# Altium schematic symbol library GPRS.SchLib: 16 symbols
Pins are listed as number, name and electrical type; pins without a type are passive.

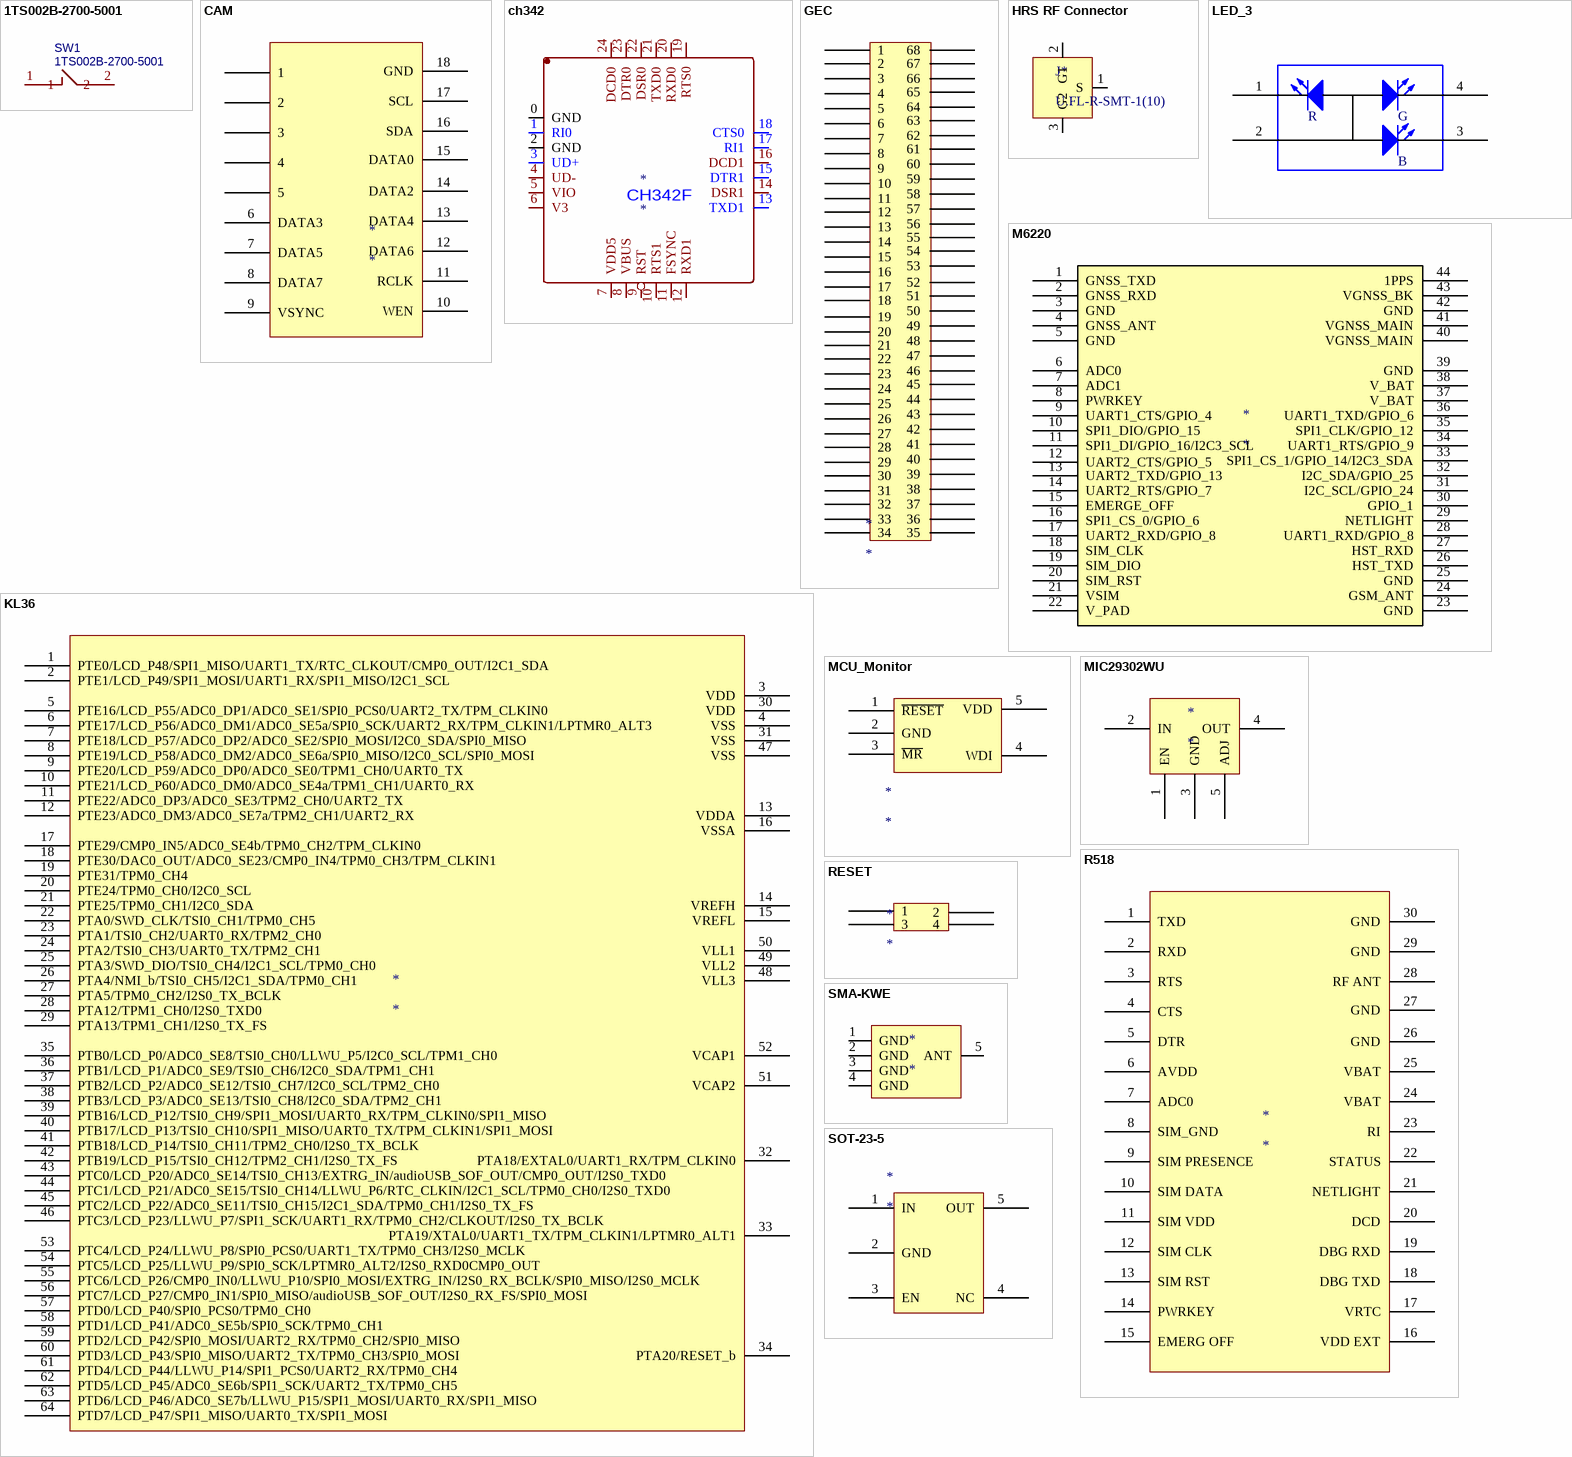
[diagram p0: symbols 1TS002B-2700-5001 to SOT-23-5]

## 1TS002B-2700-5001
designator SW1
轻触开关（贴片式，上按）; BOM_Manufacturer: HYP; Contributor: LCSC
footprint SW-SMD_L6.0-W3.5-LS8.0
pins: 1, 2

## CAM
designator *
footprint IDC2X9
pins: 4, 5, 6 DATA3, 7 DATA5, 8 DATA7, 9 VSYNC, 10 WEN, 11 RCLK, 12 DATA6, 13 DATA4, 14 DATA2, 15 DATA0, 16 SDA, 17 SCL, 18 GND, ?1 1, ?2 2, ?3 3

## ch342
designator *
footprint ch342
footprint ch342
pins: 0 GND, 1 RI0, 2 GND, 3 UD+, 4 UD-, 5 VIO, 6 V3, 7 VDD5, 8 VBUS, 9 RST, 10 RTS1, 11 FSYNC, 12 RXD1, 13 TXD1, 14 DSR1, 15 DTR1, 16 DCD1, 17 RI1, 18 CTS0, 19 RTS0, 20 RXD0, 21 TXD0, 22 DSR0, 23 DTR0, 24 DCD0

## GEC
designator *
pins: 1, 2, 3, 4, 5, 6, 7, 8, 9, 10, 11, 12, 13, 14, 15, 16, 17, 18, 19, 20, 21, 22, 23, 24, 25, 26, 27, 28, 29, 30, 31, 32, 33, 34, 35, 36, 37, 38, 39, 40, 41, 42, 43, 44, 45, 46, 47, 48, 49, 50, 51, 52, 53, 54, 55, 56, 57, 58, 59, 60, 61, 62, 63, 64, 65, 66, 67, 68

## HRS RF Connector
designator J*, comment U.FL-R-SMT-1(10)
footprint HRSRFCONNECTOR (Footprint not found)
pins: 1 S, 2 G1, 3 G2

## KL36
designator *
footprint LQFP64
pins: 1 PTE0/LCD_P48/SPI1_MISO/UART1_TX/RTC_CLKOUT/CMP0_OUT/I2C1_SDA, 2 PTE1/LCD_P49/SPI1_MOSI/UART1_RX/SPI1_MISO/I2C1_SCL, 3 VDD, 4 VSS, 5 PTE16/LCD_P55/ADC0_DP1/ADC0_SE1/SPI0_PCS0/UART2_TX/TPM_CLKIN0, 6 PTE17/LCD_P56/ADC0_DM1/ADC0_SE5a/SPI0_SCK/UART2_RX/TPM_CLKIN1/LPTMR0_ALT3, 7 PTE18/LCD_P57/ADC0_DP2/ADC0_SE2/SPI0_MOSI/I2C0_SDA/SPI0_MISO, 8 PTE19/LCD_P58/ADC0_DM2/ADC0_SE6a/SPI0_MISO/I2C0_SCL/SPI0_MOSI, 9 PTE20/LCD_P59/ADC0_DP0/ADC0_SE0/TPM1_CH0/UART0_TX, 10 PTE21/LCD_P60/ADC0_DM0/ADC0_SE4a/TPM1_CH1/UART0_RX, 11 PTE22/ADC0_DP3/ADC0_SE3/TPM2_CH0/UART2_TX, 12 PTE23/ADC0_DM3/ADC0_SE7a/TPM2_CH1/UART2_RX, 13 VDDA, 14 VREFH, 15 VREFL, 16 VSSA, 17 PTE29/CMP0_IN5/ADC0_SE4b/TPM0_CH2/TPM_CLKIN0, 18 PTE30/DAC0_OUT/ADC0_SE23/CMP0_IN4/TPM0_CH3/TPM_CLKIN1, 19 PTE31/TPM0_CH4, 20 PTE24/TPM0_CH0/I2C0_SCL, 21 PTE25/TPM0_CH1/I2C0_SDA, 22 PTA0/SWD_CLK/TSI0_CH1/TPM0_CH5, 23 PTA1/TSI0_CH2/UART0_RX/TPM2_CH0, 24 PTA2/TSI0_CH3/UART0_TX/TPM2_CH1, 25 PTA3/SWD_DIO/TSI0_CH4/I2C1_SCL/TPM0_CH0, 26 PTA4/NMI_b/TSI0_CH5/I2C1_SDA/TPM0_CH1, 27 PTA5/TPM0_CH2/I2S0_TX_BCLK, 28 PTA12/TPM1_CH0/I2S0_TXD0, 29 PTA13/TPM1_CH1/I2S0_TX_FS, 30 VDD, 31 VSS, 32 PTA18/EXTAL0/UART1_RX/TPM_CLKIN0, 33 PTA19/XTAL0/UART1_TX/TPM_CLKIN1/LPTMR0_ALT1, 34 PTA20/RESET_b, 35 PTB0/LCD_P0/ADC0_SE8/TSI0_CH0/LLWU_P5/I2C0_SCL/TPM1_CH0, 36 PTB1/LCD_P1/ADC0_SE9/TSI0_CH6/I2C0_SDA/TPM1_CH1, 37 PTB2/LCD_P2/ADC0_SE12/TSI0_CH7/I2C0_SCL/TPM2_CH0, 38 PTB3/LCD_P3/ADC0_SE13/TSI0_CH8/I2C0_SDA/TPM2_CH1, 39 PTB16/LCD_P12/TSI0_CH9/SPI1_MOSI/UART0_RX/TPM_CLKIN0/SPI1_MISO, 40 PTB17/LCD_P13/TSI0_CH10/SPI1_MISO/UART0_TX/TPM_CLKIN1/SPI1_MOSI, 41 PTB18/LCD_P14/TSI0_CH11/TPM2_CH0/I2S0_TX_BCLK, 42 PTB19/LCD_P15/TSI0_CH12/TPM2_CH1/I2S0_TX_FS, 43 PTC0/LCD_P20/ADC0_SE14/TSI0_CH13/EXTRG_IN/audioUSB_SOF_OUT/CMP0_OUT/I2S0_TXD0, 44 PTC1/LCD_P21/ADC0_SE15/TSI0_CH14/LLWU_P6/RTC_CLKIN/I2C1_SCL/TPM0_CH0/I2S0_TXD0, 45 PTC2/LCD_P22/ADC0_SE11/TSI0_CH15/I2C1_SDA/TPM0_CH1/I2S0_TX_FS, 46 PTC3/LCD_P23/LLWU_P7/SPI1_SCK/UART1_RX/TPM0_CH2/CLKOUT/I2S0_TX_BCLK, 47 VSS, 48 VLL3, 49 VLL2, 50 VLL1, 51 VCAP2, 52 VCAP1, 53 PTC4/LCD_P24/LLWU_P8/SPI0_PCS0/UART1_TX/TPM0_CH3/I2S0_MCLK, 54 PTC5/LCD_P25/LLWU_P9/SPI0_SCK/LPTMR0_ALT2/I2S0_RXD0CMP0_OUT, 55 PTC6/LCD_P26/CMP0_IN0/LLWU_P10/SPI0_MOSI/EXTRG_IN/I2S0_RX_BCLK/SPI0_MISO/I2S0_MCLK, 56 PTC7/LCD_P27/CMP0_IN1/SPI0_MISO/audioUSB_SOF_OUT/I2S0_RX_FS/SPI0_MOSI, 57 PTD0/LCD_P40/SPI0_PCS0/TPM0_CH0, 58 PTD1/LCD_P41/ADC0_SE5b/SPI0_SCK/TPM0_CH1, 59 PTD2/LCD_P42/SPI0_MOSI/UART2_RX/TPM0_CH2/SPI0_MISO, 60 PTD3/LCD_P43/SPI0_MISO/UART2_TX/TPM0_CH3/SPI0_MOSI, 61 PTD4/LCD_P44/LLWU_P14/SPI1_PCS0/UART2_RX/TPM0_CH4, 62 PTD5/LCD_P45/ADC0_SE6b/SPI1_SCK/UART2_TX/TPM0_CH5, 63 PTD6/LCD_P46/ADC0_SE7b/LLWU_P15/SPI1_MOSI/UART0_RX/SPI1_MISO, 64 PTD7/LCD_P47/SPI1_MISO/UART0_TX/SPI1_MOSI

## LED_3
designator LED_3, comment Single-Pole, Single-Throw Switch  (value not drawn)
footprint SPST-2 (Single-Pole, Single-Throw Switch; 2 Leads)
pins: 1, 2, 3, 4

## M6220
designator *
pins: 1 GNSS_TXD, 2 GNSS_RXD, 3 GND, 4 GNSS_ANT, 5 GND, 6 ADC0, 7 ADC1, 8 PWRKEY, 9 UART1_CTS/GPIO_4, 10 SPI1_DIO/GPIO_15, 11 SPI1_DI/GPIO_16/I2C3_SCL, 12 UART2_CTS/GPIO_5, 13 UART2_TXD/GPIO_13, 14 UART2_RTS/GPIO_7, 15 EMERGE_OFF, 16 SPI1_CS_0/GPIO_6, 17 UART2_RXD/GPIO_8, 18 SIM_CLK, 19 SIM_DIO, 20 SIM_RST, 21 VSIM, 22 V_PAD, 23 GND, 24 GSM_ANT, 25 GND, 26 HST_TXD, 27 HST_RXD, 28 UART1_RXD/GPIO_8, 29 NETLIGHT, 30 GPIO_1, 31 I2C_SCL/GPIO_24, 32 I2C_SDA/GPIO_25, 33 SPI1_CS_1/GPIO_14/I2C3_SDA, 34 UART1_RTS/GPIO_9, 35 SPI1_CLK/GPIO_12, 36 UART1_TXD/GPIO_6, 37 V_BAT, 38 V_BAT, 39 GND, 40 VGNSS_MAIN, 41 VGNSS_MAIN, 42 GND, 43 VGNSS_BK, 44 1PPS

## MCU_Monitor
designator *
footprint SOT-23-5
pins: 1 ~{RESET}, 2 GND, 3 ~{MR}, 4 WDI, 5 VDD

## MIC29302WU
designator *
pins: 1 EN, 2 IN, 3 GND, 4 OUT, 5 ADJ

## R518
designator *
pins: 1 TXD, 2 RXD, 3 RTS, 4 CTS, 5 DTR, 6 AVDD, 7 ADC0, 8 SIM_GND, 9 SIM PRESENCE, 10 SIM DATA, 11 SIM VDD, 12 SIM CLK, 13 SIM RST, 14 PWRKEY, 15 EMERG OFF, 16 VDD EXT, 17 VRTC, 18 DBG TXD, 19 DBG RXD, 20 DCD, 21 NETLIGHT, 22 STATUS, 23 RI, 24 VBAT, 25 VBAT, 26 GND, 27 GND, 28 RF ANT, 29 GND, 30 GND

## RESET
designator *
footprint RESET
pins: 1, 2, 3, 4

## SMA-KWE
designator *
pins: 1 GND, 2 GND, 3 GND, 4 GND, 5 ANT

## SOT-23-5
designator *
footprint SOT-23-5
pins: 1 IN, 2 GND, 3 EN, 4 NC, 5 OUT

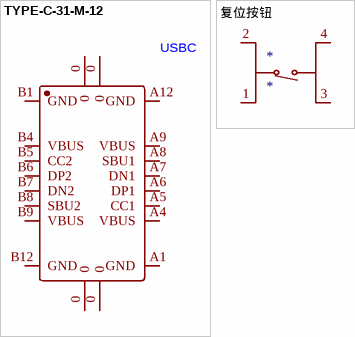
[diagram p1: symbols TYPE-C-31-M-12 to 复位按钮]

## TYPE-C-31-M-12
designator USBC
footprint USB-C_SMD-TYPE-C-31-M-12
footprint USB-C_SMD-TYPE-C-31-M-12
pins: 0, 0, 0, 0, A1 GND, A4 VBUS, A5 CC1, A6 DP1, A7 DN1, A8 SBU1, A9 VBUS, A12 GND, B1 GND, B4 VBUS, B5 CC2, B6 DP2, B7 DN2, B8 SBU2, B9 VBUS, B12 GND

## 复位按钮
designator *
pins: 1 A, 2 B, 3 C, 4 D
